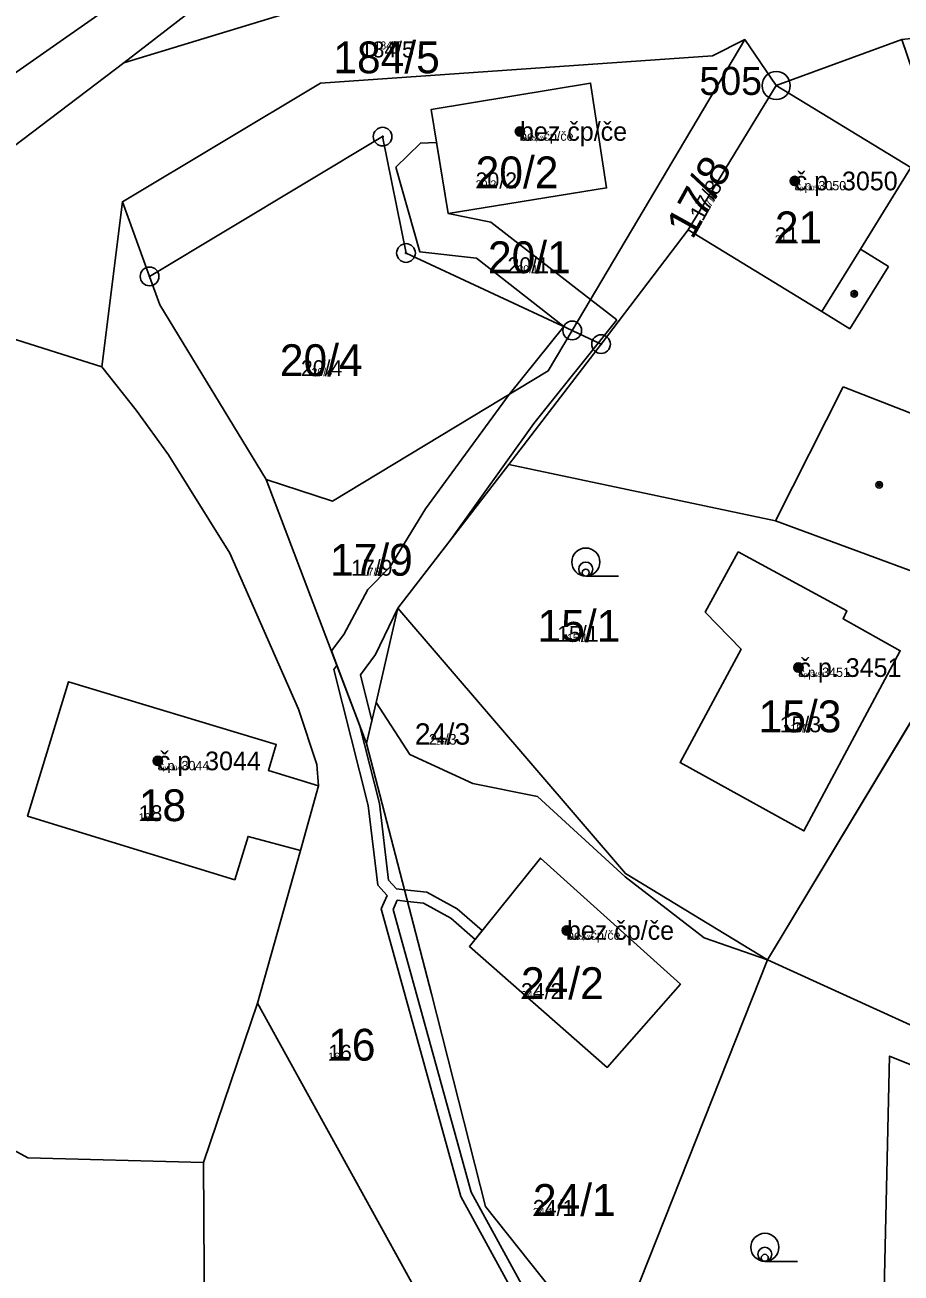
# Model space of a CAD drawing. Extents: x -759873 to -758487, y -975024 to -973516.
# Drawn here: x -759275.3 to -759228.5, y -974336.8 to -974270 of the extents above; entities that cross this region are included whole.
import ezdxf

# ---------------------------------------------------------------- set-up
doc = ezdxf.new("R2010")
doc.units = 0
for name, color, linetype in [('KAT_02_hranice parcel', 7, 'Continuous'), ('KAT_03_1000_st čísla parcelní', 7, 'Continuous'), ('KAT_03_1000_čísla parcelní', 7, 'Continuous'), ('KAT_03_1000_čísla popisná', 7, 'Continuous'), ('KAT_03_250_st čísla parcelní', 7, 'Continuous'), ('KAT_03_250_čísla parcelní', 7, 'Continuous'), ('KAT_03_250_čísla popisná', 7, 'Continuous'), ('KAT_03_500_st čísla parcelní', 7, 'Continuous'), ('KAT_03_500_čísla parcelní', 7, 'Continuous'), ('KAT_03_500_čísla popisná', 7, 'Continuous'), ('KAT_04_vnitřní kresba', 7, 'Continuous'), ('KAT_05_1000_značky kultur', 7, 'Continuous'), ('KAT_05_250_značky kultur', 7, 'Continuous'), ('KAT_05_500_značky kultur', 7, 'Continuous'), ('KAT_07_1000_značky budov', 7, 'Continuous'), ('KAT_07_250_značky budov', 7, 'Continuous'), ('KAT_07_500_značky budov', 7, 'Continuous'), ('KAT_10_věcná břemena', 7, 'Continuous'), ('KAT_11_značky bodu BP', 7, 'Continuous'), ('KAT_14_plocha_budovy', 7, 'Continuous'), ('KAT_14_plocha_pozemek', 7, 'Continuous')]:
    doc.layers.add(name, color=color, linetype=linetype)

msp = doc.modelspace()

# ---------------------------------------------------------------- linework, layer by layer
at = {"layer": 'KAT_02_hranice parcel'}
for p, q in [((-759246.04, -974286.37), (-759236.82, -974270.82)), ((-759236.82, -974270.82), (-759235.14, -974273.28)), ((-759228.43, -974270.82), (-759235.14, -974273.28)), ((-759270.07, -974279.49), (-759271.18, -974288.32)), ((-759268.62, -974283.48), (-759270.07, -974279.49)), ((-759246.04, -974286.37), (-759244.5, -974287.1)), ((-759244.5, -974287.1), (-759249.43, -974293.54)), ((-759249.43, -974293.54), (-759255.35, -974301.22)), ((-759257.03, -974308.45), (-759262.39, -974294.33)), ((-759223.86, -974300.51), (-759235.61, -974320.02)), ((-759255.35, -974301.22), (-759256.52, -974306.25)), ((-759256.52, -974306.25), (-759257.03, -974308.45)), ((-759253.56, -974321.83), (-759257.03, -974308.45)), ((-759259.59, -974310.71), (-759260.55, -974314.17)), ((-759260.55, -974314.17), (-759262.85, -974322.33)), ((-759262.85, -974322.33), (-759265.74, -974330.84)), ((-759244.28, -974356.01), (-759262.85, -974322.33)), ((-759265.74, -974330.84), (-759275.13, -974330.59))]:
    msp.add_line(p, q, dxfattribs=at)
for points in [[(-759306.36, -974248.79), (-759295.11, -974286.11), (-759271.03, -974269.26)], [(-759295.6, -974291.49), (-759269.99, -974272.06), (-759263.6, -974267.11), (-759259.68, -974266.44)], [(-759236.82, -974270.82), (-759238.54, -974271.69), (-759259.49, -974273.15), (-759270.07, -974279.49)], [(-759245.06, -974273.15), (-759244.2, -974278.75), (-759252.67, -974280.11), (-759253.58, -974274.56), (-759245.06, -974273.15)], [(-759235.14, -974273.28), (-759239.84, -974281), (-759244.5, -974287.1)], [(-759217.88, -974281.35), (-759227.95, -974277.66), (-759235.14, -974273.28)], [(-759268.62, -974283.48), (-759256.17, -974276.01), (-759254.92, -974282.23), (-759246.04, -974286.37)], [(-759262.39, -974294.33), (-759268.07, -974285), (-759268.62, -974283.48)], [(-759271.18, -974288.32), (-759278.22, -974286.08), (-759287.83, -974293.22), (-759290.32, -974296.86), (-759293.62, -974299.26)], [(-759246.04, -974286.37), (-759247.32, -974288.53), (-759258.85, -974295.49), (-759262.39, -974294.33)], [(-759271.18, -974288.32), (-759269.33, -974290.63), (-759267.61, -974293.02), (-759264.33, -974298.27), (-759260.66, -974306.61), (-759259.68, -974309.57), (-759259.59, -974310.71)], [(-759249.43, -974293.54), (-759235.18, -974296.55), (-759226.87, -974299.61)], [(-759237.18, -974298.2), (-759231.37, -974301.35), (-759231.56, -974301.79), (-759228.51, -974303.49), (-759233.66, -974313.12), (-759240.28, -974309.47), (-759237.02, -974303.41), (-759238.93, -974301.42), (-759237.18, -974298.2)], [(-759255.35, -974301.22), (-759243.2, -974315.4), (-759235.61, -974320.02)], [(-759259.59, -974310.71), (-759262.27, -974309.89), (-759261.85, -974308.51), (-759272.95, -974305.15), (-759275.14, -974312.33), (-759264.07, -974315.73), (-759263.36, -974313.42), (-759260.55, -974314.17)], [(-759235.61, -974320.02), (-759238.99, -974318.84), (-759243.21, -974315.57), (-759247.9, -974311.28), (-759251.35, -974310.58), (-759254.71, -974309.04), (-759256.52, -974306.25)], [(-759275.13, -974330.59), (-759276.47, -974329.86), (-759280.62, -974323.73), (-759282.44, -974321.04), (-759283.23, -974320.62), (-759297.93, -974312.94)], [(-759240.26, -974321.31), (-759244.17, -974325.76), (-759251.53, -974319.3), (-759247.74, -974314.57), (-759240.26, -974321.31)], [(-759235.61, -974320.02), (-759243.22, -974339.24), (-759244.1, -974341.47)], [(-759217.5, -974328.24), (-759228.38, -974323.31), (-759235.61, -974320.02)], [(-759244.1, -974341.47), (-759250.68, -974333.2), (-759253.56, -974321.83)], [(-759224.77, -974347.59), (-759229.56, -974346.28), (-759229.08, -974325.16), (-759216.63, -974330.16), (-759217.5, -974328.24)], [(-759265.74, -974330.84), (-759265.67, -974342.52), (-759265.5, -974344.74), (-759265.03, -974350.94)]]:
    msp.add_lwpolyline(points, dxfattribs=at)
at = {"layer": 'KAT_03_1000_čísla popisná'}
for centre in [(-759248.83, -974275.73), (-759234.15, -974278.38), (-759233.95, -974304.39), (-759268.18, -974309.38), (-759246.32, -974318.44)]:
    msp.add_circle(centre, 0.25, dxfattribs=at)
at = {"layer": 'KAT_03_250_čísla popisná'}
for centre in [(-759248.83, -974275.73), (-759234.15, -974278.38), (-759233.95, -974304.39), (-759268.18, -974309.38), (-759246.32, -974318.44)]:
    msp.add_circle(centre, 0.0625, dxfattribs=at)
at = {"layer": 'KAT_03_500_čísla popisná'}
for centre in [(-759248.83, -974275.73), (-759234.15, -974278.38), (-759233.95, -974304.39), (-759268.18, -974309.38), (-759246.32, -974318.44)]:
    msp.add_circle(centre, 0.125, dxfattribs=at)
at = {"layer": 'KAT_04_vnitřní kresba'}
for p, q in [((-759269.99, -974272.06), (-759253.79, -974267.12)), ((-759230.64, -974282.02), (-759227.95, -974277.66)), ((-759239.84, -974281), (-759232.7, -974285.35)), ((-759232.7, -974285.35), (-759230.64, -974282.02)), ((-759230.64, -974282.02), (-759229.14, -974282.95)), ((-759231.2, -974286.28), (-759229.14, -974282.95)), ((-759232.7, -974285.35), (-759231.2, -974286.28)), ((-759235.18, -974296.55), (-759231.57, -974289.39)), ((-759231.57, -974289.39), (-759224.07, -974292.3))]:
    msp.add_line(p, q, dxfattribs=at)
at = {"layer": 'KAT_05_1000_značky kultur'}
for p, q in [((-759245.313, -974299.5), (-759243.563, -974299.5)), ((-759235.743, -974336.13), (-759233.993, -974336.13))]:
    msp.add_line(p, q, dxfattribs=at)
for centre in [(-759245.313, -974298.75), (-759235.743, -974335.38)]:
    msp.add_circle(centre, 0.75, dxfattribs=at)
at = {"layer": 'KAT_05_250_značky kultur'}
for p, q in [((-759245.318, -974299.5), (-759244.881, -974299.5)), ((-759235.748, -974336.13), (-759235.311, -974336.13))]:
    msp.add_line(p, q, dxfattribs=at)
for centre in [(-759245.318, -974299.312), (-759235.748, -974335.942)]:
    msp.add_circle(centre, 0.187, dxfattribs=at)
at = {"layer": 'KAT_05_500_značky kultur'}
for p, q in [((-759245.317, -974299.5), (-759244.442, -974299.5)), ((-759235.747, -974336.13), (-759234.872, -974336.13))]:
    msp.add_line(p, q, dxfattribs=at)
for centre in [(-759245.316, -974299.125), (-759235.746, -974335.755)]:
    msp.add_circle(centre, 0.375, dxfattribs=at)
at = {"layer": 'KAT_07_1000_značky budov'}
for centre in [(-759248.837, -974275.729), (-759234.157, -974278.379), (-759230.967, -974284.409), (-759229.637, -974294.619), (-759233.957, -974304.389), (-759268.187, -974309.379), (-759246.327, -974318.439)]:
    msp.add_circle(centre, 0.175, dxfattribs=at)
at = {"layer": 'KAT_07_250_značky budov'}
for centre in [(-759248.832, -974275.73), (-759234.152, -974278.38), (-759230.962, -974284.41), (-759229.632, -974294.62), (-759233.952, -974304.39), (-759268.182, -974309.38), (-759246.322, -974318.44)]:
    msp.add_circle(centre, 0.0437, dxfattribs=at)
at = {"layer": 'KAT_07_500_značky budov'}
for centre in [(-759248.833, -974275.73), (-759234.153, -974278.38), (-759230.963, -974284.41), (-759229.633, -974294.62), (-759233.953, -974304.39), (-759268.183, -974309.38), (-759246.323, -974318.44)]:
    msp.add_circle(centre, 0.0875, dxfattribs=at)
at = {"layer": 'KAT_10_věcná břemena'}
for points in [[(-759243.65, -974285.81), (-759245.06, -974284.72), (-759250.38, -974280.59), (-759252.67, -974280.11), (-759253.29, -974276.33), (-759254.15, -974276.35), (-759255.46, -974277.64), (-759254.18, -974282.17), (-759251.16, -974282.51), (-759246.49, -974286.15), (-759249.41, -974289.79), (-759253.87, -974295.91), (-759255.78, -974299.02), (-759256.96, -974300.21), (-759258.25, -974302.62), (-759258.91, -974303.5), (-759257.03, -974308.45), (-759256.74, -974307.22), (-759257.36, -974304.78), (-759256.55, -974303.7), (-759255.35, -974301.22), (-759252.52, -974297.55), (-759248.09, -974291.35)], [(-759243.16, -974351), (-759245.15, -974354.43), (-759244.8, -974355.06), (-759242.6, -974351.24), (-759242.06, -974349.59), (-759251.43, -974332.44), (-759255.6, -974317.32), (-759255.39, -974316.83), (-759254.84, -974316.89), (-759255, -974316.27), (-759255.43, -974316.22), (-759255.85, -974315.76), (-759256.34, -974311.66), (-759257.41, -974307.46), (-759258.61, -974304.28), (-759258.78, -974304.49), (-759256.94, -974311.76), (-759256.43, -974316.02), (-759255.93, -974316.57), (-759256.24, -974317.28), (-759251.99, -974332.66), (-759242.72, -974349.65)], [(-759255, -974316.27), (-759254.84, -974316.89), (-759253.98, -974316.98), (-759252.52, -974317.78), (-759251.22, -974318.92), (-759250.85, -974318.45), (-759252.18, -974317.28), (-759253.8, -974316.4)]]:
    msp.add_lwpolyline(points, close=True, dxfattribs=at)
at = {"layer": 'KAT_11_značky bodu BP'}
for centre, radius in [((-759235.14, -974273.28), 0.75), ((-759235.14, -974273.28), 0.03), ((-759256.17, -974276.01), 0.5), ((-759256.17, -974276.01), 0.0303), ((-759254.92, -974282.23), 0.5), ((-759254.92, -974282.23), 0.0303), ((-759268.62, -974283.48), 0.5), ((-759268.62, -974283.48), 0.0303), ((-759246.04, -974286.37), 0.5), ((-759246.04, -974286.37), 0.0303), ((-759244.5, -974287.1), 0.5), ((-759244.5, -974287.1), 0.0303)]:
    msp.add_circle(centre, radius, dxfattribs=at)
at = {"layer": 'KAT_14_plocha_budovy'}
for points in [[(-759253.58, -974274.56), (-759252.67, -974280.11), (-759244.2, -974278.75), (-759245.06, -974273.15)], [(-759235.14, -974273.28), (-759239.84, -974281), (-759232.7, -974285.35), (-759230.64, -974282.02), (-759227.95, -974277.66)], [(-759237.18, -974298.2), (-759238.93, -974301.42), (-759237.02, -974303.41), (-759240.28, -974309.47), (-759233.66, -974313.12), (-759228.51, -974303.49), (-759231.56, -974301.79), (-759231.37, -974301.35)], [(-759275.14, -974312.33), (-759264.07, -974315.73), (-759263.36, -974313.42), (-759260.55, -974314.17), (-759259.59, -974310.71), (-759262.27, -974309.89), (-759261.85, -974308.51), (-759272.95, -974305.15)], [(-759251.53, -974319.3), (-759244.17, -974325.76), (-759240.26, -974321.31), (-759247.74, -974314.57)]]:
    msp.add_lwpolyline(points, close=True, dxfattribs=at)
at = {"layer": 'KAT_14_plocha_pozemek'}
for points in [[(-759306.36, -974248.79), (-759307.7, -974244.36), (-759315.77, -974246.81), (-759315.65, -974247.85), (-759310.07, -974249.57), (-759314.38, -974261.38), (-759308.39, -974270.99), (-759301.29, -974282.37), (-759295.6, -974291.49), (-759269.99, -974272.06), (-759263.6, -974267.11), (-759259.68, -974266.44), (-759261.58, -974266.43), (-759263.21, -974266.18), (-759264.23, -974266.16), (-759264.71, -974266.19), (-759270.6, -974268.96), (-759271.03, -974269.26), (-759295.11, -974286.11)], [(-759290.27, -974260.55), (-759299.02, -974263.24), (-759303.73, -974247.93), (-759306.36, -974248.79), (-759295.11, -974286.11), (-759271.03, -974269.26), (-759275.96, -974255.96)], [(-759238.54, -974271.69), (-759259.49, -974273.15), (-759270.07, -974279.49), (-759268.62, -974283.48), (-759256.17, -974276.01), (-759254.92, -974282.23), (-759246.04, -974286.37), (-759236.82, -974270.82)], [(-759246.04, -974286.37), (-759244.5, -974287.1), (-759239.84, -974281), (-759235.14, -974273.28), (-759236.82, -974270.82)], [(-759245.06, -974273.15), (-759244.2, -974278.75), (-759252.67, -974280.11), (-759253.58, -974274.56)], [(-759245.06, -974273.15), (-759253.58, -974274.56), (-759252.67, -974280.11), (-759244.2, -974278.75)], [(-759224.07, -974292.3), (-759217.88, -974281.35), (-759227.95, -974277.66), (-759235.14, -974273.28), (-759239.84, -974281), (-759244.5, -974287.1), (-759249.43, -974293.54), (-759235.18, -974296.55), (-759226.87, -974299.61)], [(-759262.39, -974294.33), (-759258.85, -974295.49), (-759247.32, -974288.53), (-759246.04, -974286.37), (-759254.92, -974282.23), (-759256.17, -974276.01), (-759268.62, -974283.48), (-759268.07, -974285)], [(-759269.33, -974290.63), (-759267.61, -974293.02), (-759264.33, -974298.27), (-759260.66, -974306.61), (-759259.68, -974309.57), (-759259.59, -974310.71), (-759260.55, -974314.17), (-759262.85, -974322.33), (-759244.28, -974356.01), (-759239.65, -974353.33), (-759239.05, -974353.05), (-759236.02, -974351.64), (-759244.1, -974341.47), (-759250.68, -974333.2), (-759253.56, -974321.83), (-759257.03, -974308.45), (-759262.39, -974294.33), (-759268.07, -974285), (-759268.62, -974283.48), (-759270.07, -974279.49), (-759271.18, -974288.32)], [(-759262.39, -974294.33), (-759257.03, -974308.45), (-759256.52, -974306.25), (-759255.35, -974301.22), (-759249.43, -974293.54), (-759244.5, -974287.1), (-759246.04, -974286.37), (-759247.32, -974288.53), (-759258.85, -974295.49)], [(-759255.35, -974301.22), (-759243.2, -974315.4), (-759235.61, -974320.02), (-759223.86, -974300.51), (-759226.87, -974299.61), (-759235.18, -974296.55), (-759249.43, -974293.54)], [(-759237.18, -974298.2), (-759231.37, -974301.35), (-759231.56, -974301.79), (-759228.51, -974303.49), (-759233.66, -974313.12), (-759240.28, -974309.47), (-759237.02, -974303.41), (-759238.93, -974301.42)], [(-759237.18, -974298.2), (-759238.93, -974301.42), (-759237.02, -974303.41), (-759240.28, -974309.47), (-759233.66, -974313.12), (-759228.51, -974303.49), (-759231.56, -974301.79), (-759231.37, -974301.35)], [(-759210.51, -974305.67), (-759223.86, -974300.51), (-759235.61, -974320.02), (-759228.38, -974323.31), (-759217.5, -974328.24), (-759216.4, -974327.19), (-759223.76, -974323.13), (-759218.45, -974313.52), (-759216.15, -974314.79), (-759213.69, -974310.96), (-759208.71, -974313.99), (-759198.76, -974315.57), (-759191.06, -974317.77), (-759190.59, -974310.66)], [(-759256.52, -974306.25), (-759254.71, -974309.04), (-759251.35, -974310.58), (-759247.9, -974311.28), (-759243.21, -974315.57), (-759238.99, -974318.84), (-759235.61, -974320.02), (-759243.2, -974315.4), (-759255.35, -974301.22)], [(-759259.59, -974310.71), (-759262.27, -974309.89), (-759261.85, -974308.51), (-759272.95, -974305.15), (-759275.14, -974312.33), (-759264.07, -974315.73), (-759263.36, -974313.42), (-759260.55, -974314.17)], [(-759256.52, -974306.25), (-759257.03, -974308.45), (-759253.56, -974321.83), (-759250.68, -974333.2), (-759244.1, -974341.47), (-759243.22, -974339.24), (-759235.61, -974320.02), (-759238.99, -974318.84), (-759243.21, -974315.57), (-759247.9, -974311.28), (-759251.35, -974310.58), (-759254.71, -974309.04)], [(-759275.13, -974330.59), (-759276.47, -974329.86), (-759280.62, -974323.73), (-759282.44, -974321.04), (-759283.23, -974320.62), (-759297.93, -974312.94), (-759297.91, -974317.24), (-759297.5, -974320.18), (-759297.42, -974320.63), (-759294.88, -974335.08), (-759290.88, -974335.09), (-759284.25, -974335.11), (-759280.36, -974342.49), (-759280.6, -974350.56), (-759265.03, -974350.94), (-759265.5, -974344.74), (-759265.67, -974342.52), (-759265.74, -974330.84)], [(-759240.26, -974321.31), (-759244.17, -974325.76), (-759251.53, -974319.3), (-759247.74, -974314.57)], [(-759240.26, -974321.31), (-759247.74, -974314.57), (-759251.53, -974319.3), (-759244.17, -974325.76)], [(-759216.63, -974330.16), (-759217.5, -974328.24), (-759228.38, -974323.31), (-759235.61, -974320.02), (-759243.22, -974339.24), (-759244.1, -974341.47), (-759236.02, -974351.64), (-759229, -974348.38), (-759224.77, -974347.59), (-759229.56, -974346.28), (-759229.08, -974325.16)], [(-759265.74, -974330.84), (-759265.67, -974342.52), (-759265.5, -974344.74), (-759265.03, -974350.94), (-759264.01, -974358.69), (-759252.89, -974364.02), (-759252.04, -974364.43), (-759251.38, -974361.09), (-759244.28, -974356.01), (-759262.85, -974322.33)], [(-759224.77, -974347.59), (-759223.96, -974348.06), (-759210.44, -974355.81), (-759209.27, -974359.71), (-759209.54, -974367.85), (-759209.96, -974369), (-759206.27, -974369.15), (-759197.19, -974369.51), (-759193.58, -974369.65), (-759193.89, -974359.92), (-759194.5, -974349.88), (-759198.49, -974349.74), (-759196.17, -974336.14), (-759217.5, -974328.24), (-759216.63, -974330.16), (-759229.08, -974325.16), (-759229.56, -974346.28)]]:
    msp.add_lwpolyline(points, close=True, dxfattribs=at)
for points in [[(-759190.18, -974262.03), (-759212.16, -974265.84), (-759220.4, -974266.32), (-759237.84, -974266.99), (-759253.59, -974265.4), (-759252.94, -974265.96), (-759252.86, -974266.3), (-759257.25, -974266.45), (-759259.68, -974266.44), (-759263.6, -974267.11), (-759269.99, -974272.06), (-759295.6, -974291.49), (-759302.89, -974294.94), (-759308.64, -974296.79), (-759307.1, -974307.3), (-759305.07, -974311.23), (-759302.64, -974322.45), (-759303.06, -974322.52), (-759302.32, -974328.54), (-759301.4, -974333.76), (-759301.15, -974335.03), (-759300.63, -974337.72)], [(-759294.1, -974339.54), (-759294.7, -974336.11), (-759294.88, -974335.08), (-759297.42, -974320.63), (-759297.5, -974320.18), (-759298.95, -974312.41), (-759297.19, -974308.22), (-759295.92, -974305.18), (-759295.58, -974302.76), (-759295.25, -974300.45), (-759293.62, -974299.26), (-759290.32, -974296.86), (-759287.83, -974293.22), (-759278.22, -974286.08), (-759271.18, -974288.32), (-759270.07, -974279.49), (-759259.49, -974273.15), (-759238.54, -974271.69), (-759236.82, -974270.82), (-759235.14, -974273.28), (-759228.43, -974270.82), (-759182.46, -974265.89)], [(-759189.8, -974283.73), (-759195.89, -974284.15), (-759208.4, -974281.61), (-759215.95, -974278.9), (-759227.24, -974274.32), (-759228.43, -974270.82), (-759235.14, -974273.28), (-759227.95, -974277.66), (-759217.88, -974281.35), (-759212.45, -974282.98), (-759208.98, -974283.62), (-759198.14, -974285.48), (-759198.3, -974286.21), (-759198.15, -974286.24), (-759198.63, -974288.77), (-759196.06, -974289.51), (-759192.55, -974296.61), (-759190.59, -974310.66), (-759191.06, -974317.77), (-759193.15, -974325.52), (-759196.17, -974336.14), (-759198.49, -974349.74)], [(-759276.47, -974329.86), (-759275.13, -974330.59), (-759265.74, -974330.84), (-759262.85, -974322.33), (-759260.55, -974314.17), (-759263.36, -974313.42), (-759264.07, -974315.73), (-759275.14, -974312.33), (-759272.95, -974305.15), (-759261.85, -974308.51), (-759262.27, -974309.89), (-759259.59, -974310.71), (-759259.68, -974309.57), (-759260.66, -974306.61), (-759264.33, -974298.27), (-759267.61, -974293.02), (-759269.33, -974290.63), (-759271.18, -974288.32), (-759278.22, -974286.08)]]:
    msp.add_lwpolyline(points, dxfattribs=at)

# ---------------------------------------------------------------- texts
at = {"layer": 'KAT_03_1000_st čísla parcelní'}
for s, p in [('20/2', (-759251.2, -974278.77)), ('21', (-759235.21, -974281.71)), ('15/3', (-759236.081, -974307.85)), ('18', (-759269.2, -974312.6)), ('24/2', (-759248.78, -974322.11)), ('24/1', (-759248.14, -974333.7))]:
    msp.add_text(s, height=1.7, dxfattribs=at).set_placement(p)
at = {"layer": 'KAT_03_1000_čísla parcelní'}
for s, height, p in [('184/5', 1.7, (-759258.803, -974272.623)), ('20/1', 1.7, (-759250.541, -974283.309)), ('20/4', 1.7, (-759261.661, -974288.809)), ('17/9', 1.7, (-759258.981, -974299.48)), ('15/1', 1.7, (-759247.891, -974303.01)), ('24/3', 1.139, (-759254.451, -974308.509)), ('16', 1.7, (-759259.08, -974325.4))]:
    msp.add_text(s, height=height, dxfattribs=at).set_placement(p)
msp.add_text('17/8', height=1.7, rotation=61, dxfattribs=at).set_placement((-759239.613, -974281.562))
at = {"layer": 'KAT_03_1000_čísla popisná'}
for s, p in [('bez čp/če', (-759248.83, -974276.23)), ('č.p. 3050', (-759234.15, -974278.88)), ('č.p. 3451', (-759233.95, -974304.89)), ('č.p. 3044', (-759268.18, -974309.88)), ('bez čp/če', (-759246.32, -974318.94))]:
    msp.add_text(s, height=1, dxfattribs=at).set_placement(p)
at = {"layer": 'KAT_03_250_st čísla parcelní'}
for s, p in [('20/2', (-759251.2, -974278.77)), ('21', (-759235.21, -974281.71)), ('15/3', (-759234.389, -974307.85)), ('18', (-759269.2, -974312.6)), ('24/2', (-759248.78, -974322.11)), ('24/1', (-759248.14, -974333.7))]:
    msp.add_text(s, height=0.425, dxfattribs=at).set_placement(p)
at = {"layer": 'KAT_03_250_čísla parcelní'}
for s, height, p in [('184/5', 0.425, (-759256.611, -974271.348)), ('20/1', 0.425, (-759248.972, -974283.309)), ('20/4', 0.425, (-759259.972, -974288.809)), ('17/9', 0.425, (-759257.288, -974299.48)), ('15/1', 0.425, (-759246.322, -974303.01)), ('24/3', 0.2847, (-759253.317, -974308.509)), ('16', 0.425, (-759259.08, -974325.4))]:
    msp.add_text(s, height=height, dxfattribs=at).set_placement(p)
msp.add_text('17/8', height=0.425, rotation=61, dxfattribs=at).set_placement((-759238.792, -974280.081))
at = {"layer": 'KAT_03_250_čísla popisná'}
for s, p in [('bez čp/če', (-759248.83, -974276.23)), ('č.p. 3050', (-759234.15, -974278.88)), ('č.p. 3451', (-759233.95, -974304.89)), ('č.p. 3044', (-759268.18, -974309.88)), ('bez čp/če', (-759246.32, -974318.94))]:
    msp.add_text(s, height=0.25, dxfattribs=at).set_placement(p)
at = {"layer": 'KAT_03_500_st čísla parcelní'}
for s, p in [('20/2', (-759251.2, -974278.77)), ('21', (-759235.21, -974281.71)), ('15/3', (-759234.953, -974307.85)), ('18', (-759269.2, -974312.6)), ('24/2', (-759248.78, -974322.11)), ('24/1', (-759248.14, -974333.7))]:
    msp.add_text(s, height=0.85, dxfattribs=at).set_placement(p)
at = {"layer": 'KAT_03_500_čísla parcelní'}
for s, height, p in [('184/5', 0.85, (-759257.341, -974271.773)), ('20/1', 0.85, (-759249.495, -974283.309)), ('20/4', 0.85, (-759260.535, -974288.809)), ('17/9', 0.85, (-759257.852, -974299.48)), ('15/1', 0.85, (-759246.845, -974303.01)), ('24/3', 0.5695, (-759253.695, -974308.509)), ('16', 0.85, (-759259.08, -974325.4))]:
    msp.add_text(s, height=height, dxfattribs=at).set_placement(p)
msp.add_text('17/8', height=0.85, rotation=61, dxfattribs=at).set_placement((-759239.066, -974280.575))
at = {"layer": 'KAT_03_500_čísla popisná'}
for s, p in [('bez čp/če', (-759248.83, -974276.23)), ('č.p. 3050', (-759234.15, -974278.88)), ('č.p. 3451', (-759233.95, -974304.89)), ('č.p. 3044', (-759268.18, -974309.88)), ('bez čp/če', (-759246.32, -974318.94))]:
    msp.add_text(s, height=0.5, dxfattribs=at).set_placement(p)
at = {"layer": 'KAT_11_značky bodu BP'}
msp.add_text('505', height=1.5, dxfattribs=at).set_placement((-759239.243, -974273.78))

doc.saveas('drawing.dxf')
